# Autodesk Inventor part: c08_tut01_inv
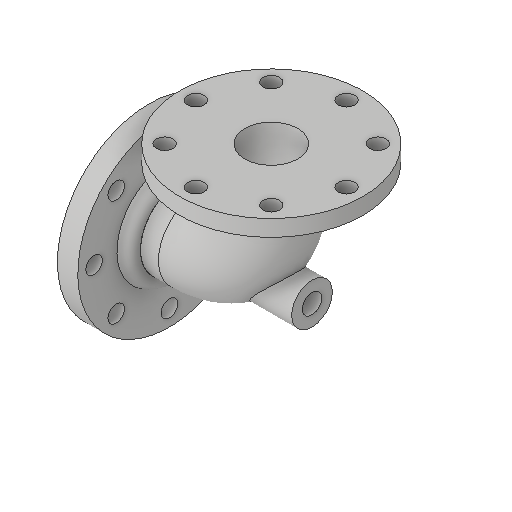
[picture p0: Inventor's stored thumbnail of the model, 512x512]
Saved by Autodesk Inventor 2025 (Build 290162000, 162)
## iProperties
Created: 2015-03
Part Number: c08_tut01_inv
Material: Generic
Document SubType Name: Modeling
Designer: Sandeep
Density: 1 g/cm^3
Appearance: Default
Author: Sandeep
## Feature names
1. Sweep1
2. Shell1
3. Extrusion1
4. Extrusion2
5. Extrusion3
6. Extrusion4
7. Fillet1
8. Extrusion5
9. Circular Pattern1
10. Extrusion6
11. Circular Pattern2
12. Extrusion7
13. Hole1
## Parameters: d1 = 35 mm, d2 = 35 mm, d4 = 97 mm, d5 = 0, d6 = 0, d7 = 16 mm, d8 = 225 mm, d10 = 0, d11 = 225 mm, d13 = 25 mm, d14 = 0, d15 = 86 mm, d16 = 22 mm, d17 = 0, d18 = 129 mm, d19 = 16 mm, d20 = 0, d21 = 16 mm, d22 = 185 mm, d23 = 20.5 mm, d24 = 0, d25 = 0, d27 = 360 deg, d29 = 185 mm, d30 = 20.5 mm, d31 = 16 mm, d32 = 0, d34 = 360 deg, d37 = 175 mm, d39 = 145 mm, d40 = 16 mm, d41 = 0, d45 = 6 mm, d46 = 24 mm, d47 = 28 mm, d48 = 90 deg, d49 = 8 mm, d50 = 118 deg
